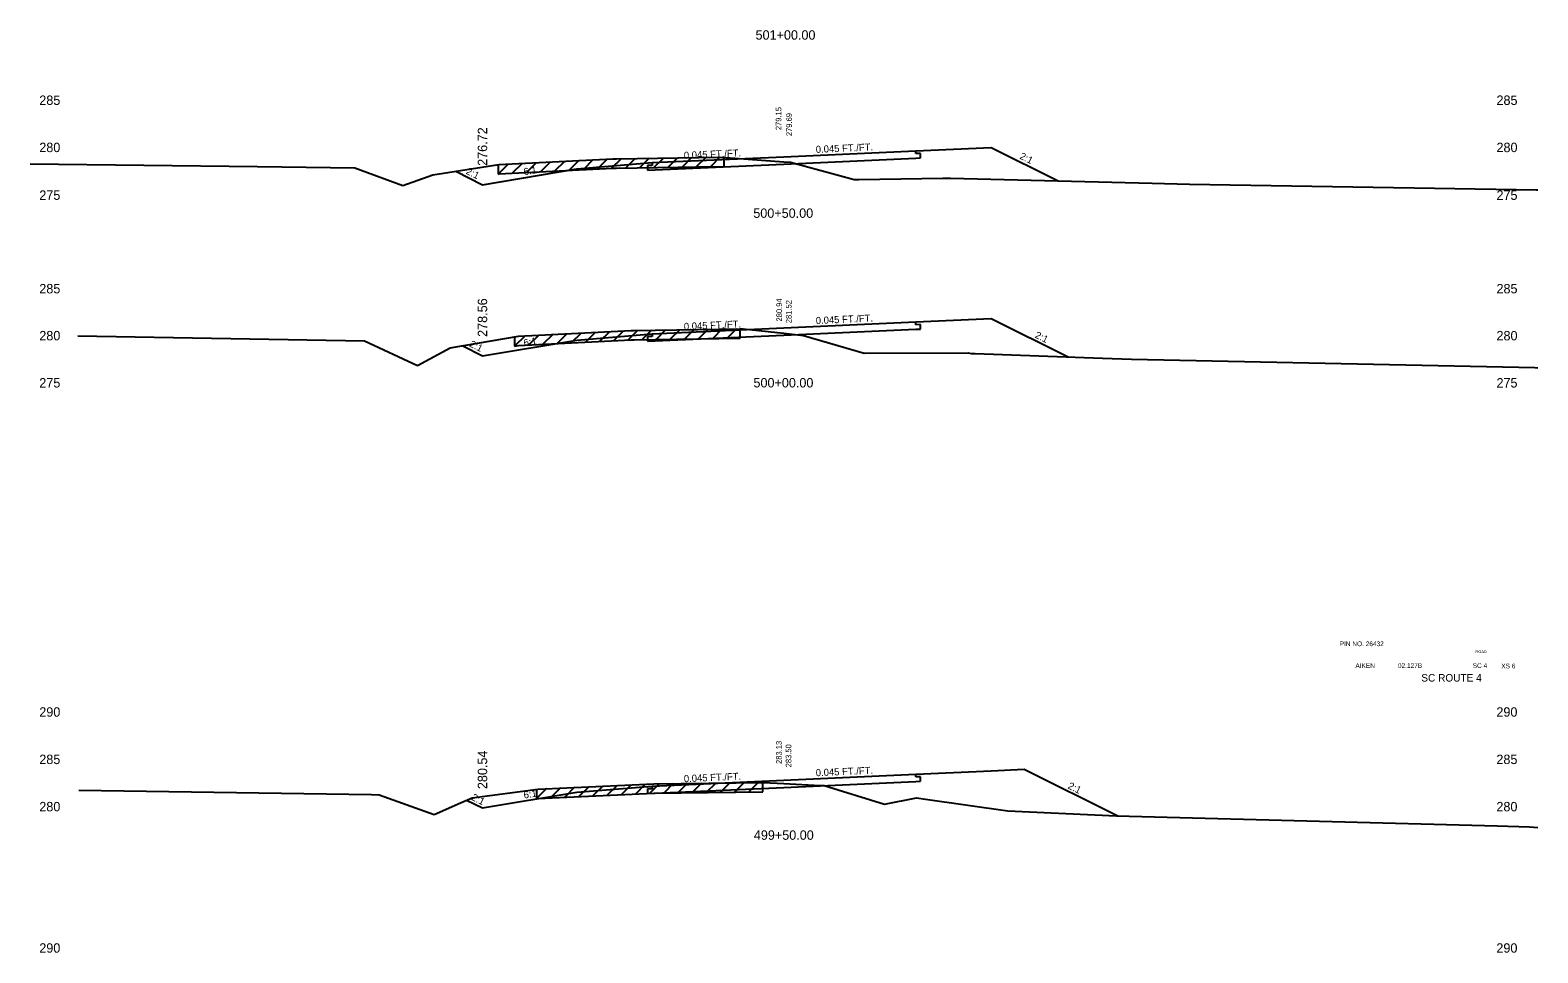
# Model space of a CAD drawing. Extents: x 883 to 1160, y 1002 to 4323.
# Drawn here: x 1000 to 1160, y 1645.2 to 1743.1 of the extents above; entities that cross this region are included whole.
import ezdxf

# ---------------------------------------------------------------- set-up
doc = ezdxf.new("R2010")
doc.units = 0
for name, color, linetype in [('Level 1', 7, 'Continuous'), ('Level 10', 7, 'Continuous'), ('Level 11', 7, 'Continuous'), ('Level 12', 7, 'Continuous'), ('Level 3', 7, 'Continuous'), ('Level 32', 7, 'Continuous'), ('Level 33', 7, 'Continuous'), ('Level 59', 7, 'Continuous'), ('Level 6', 7, 'Continuous'), ('Level 60', 7, 'Continuous'), ('Level 61', 7, 'Continuous'), ('Level 7', 7, 'Continuous')]:
    doc.layers.add(name, color=color, linetype=linetype)

msp = doc.modelspace()

# ---------------------------------------------------------------- linework, layer by layer
at = {"layer": 'Level 11'}
for p, q in [((1094, 1730.02), (1094, 1730.32)), ((1094.5, 1730.04), (1094, 1730.02)), ((1094.5, 1729.56), (1094.5, 1730.04)), ((1094, 1729.54), (1094.5, 1729.56)), ((1094, 1711.85), (1094, 1712.15)), ((1094.5, 1711.87), (1094, 1711.85)), ((1094, 1711.37), (1094.5, 1711.39)), ((1094.5, 1711.39), (1094.5, 1711.87)), ((1094, 1663.83), (1094, 1664.13)), ((1094.5, 1663.85), (1094, 1663.83)), ((1094, 1663.35), (1094.5, 1663.37)), ((1094.5, 1663.37), (1094.5, 1663.85))]:
    msp.add_line(p, q, dxfattribs=at)
at = {"layer": 'Level 12'}
for p, q in [((1065.5, 1728.28), (1080, 1728.91)), ((1066, 1728.76), (1065.5, 1728.76)), ((1065.5, 1728.76), (1065.5, 1728.28)), ((1066, 1729.06), (1066, 1728.76)), ((1080, 1728.91), (1094, 1729.54)), ((1065.5, 1710.11), (1080, 1710.74)), ((1066, 1710.59), (1065.5, 1710.59)), ((1065.5, 1710.59), (1065.5, 1710.11)), ((1066, 1710.89), (1066, 1710.59)), ((1080, 1710.74), (1094, 1711.37)), ((1065.5, 1662.09), (1080, 1662.72)), ((1066, 1662.57), (1065.5, 1662.57)), ((1065.5, 1662.57), (1065.5, 1662.09)), ((1066, 1662.87), (1066, 1662.57)), ((1080, 1662.72), (1094, 1663.35))]:
    msp.add_line(p, q, dxfattribs=at)
at = {"layer": 'Level 59'}
for p, q in [((1066, 1729.06), (1080, 1729.69)), ((1080, 1729.69), (1094, 1730.32)), ((1080, 1711.52), (1094, 1712.15)), ((1066, 1710.89), (1080, 1711.52)), ((1080, 1663.5), (1094, 1664.13)), ((1066, 1662.87), (1080, 1663.5))]:
    msp.add_line(p, q, dxfattribs=at)
at = {"layer": 'Level 6'}
for p, q in [((1094, 1730.32), (1102, 1730.68)), ((1058, 1728.39), (1066, 1729.06)), ((1094, 1712.15), (1102, 1712.51)), ((1058, 1710.22), (1066, 1710.89)), ((1094, 1664.13), (1102, 1664.49)), ((1102, 1664.49), (1105.5, 1664.65)), ((1058, 1662.2), (1066, 1662.87))]:
    msp.add_line(p, q, dxfattribs=at)
at = {"layer": 'Level 60'}
for p, q in [((1062.22, 1729.47), (1073.11, 1729.64)), ((1073.11, 1729.64), (1073.81, 1729.62)), ((1073.81, 1729.62), (1080, 1729.15)), ((1000, 1728.92), (1024.13, 1728.65)), ((1024.13, 1728.65), (1034.44, 1728.51)), ((1034.44, 1728.51), (1039.55, 1726.65)), ((1042.74, 1727.76), (1049.73, 1728.86)), ((1049.73, 1728.86), (1061.84, 1729.46)), ((1061.84, 1729.46), (1062.22, 1729.47)), ((1080, 1729.15), (1080.68, 1729.1)), ((1080.68, 1729.1), (1087.44, 1727.28)), ((1039.55, 1726.65), (1042.74, 1727.76)), ((1087.44, 1727.28), (1087.94, 1727.28)), ((1087.94, 1727.28), (1096.85, 1727.43)), ((1096.85, 1727.43), (1097.68, 1727.4)), ((1097.68, 1727.4), (1119.07, 1726.88)), ((1119.07, 1726.88), (1123.03, 1726.79)), ((1123.03, 1726.79), (1159.87, 1726.19)), ((1159.87, 1726.19), (1160, 1726.18)), ((1005.06, 1710.68), (1035.47, 1710.13)), ((1044.57, 1709.38), (1051.82, 1710.65)), ((1051.82, 1710.65), (1063.78, 1711.23)), ((1063.78, 1711.23), (1064.1, 1711.24)), ((1064.1, 1711.24), (1075.33, 1711.43)), ((1075.33, 1711.43), (1075.66, 1711.43)), ((1075.66, 1711.43), (1080, 1710.94)), ((1080, 1710.94), (1082.07, 1710.72)), ((1082.07, 1710.72), (1088.5, 1708.83)), ((1035.47, 1710.13), (1041.1, 1707.53)), ((1041.1, 1707.53), (1044.57, 1709.38)), ((1088.5, 1708.83), (1099.56, 1708.86)), ((1099.56, 1708.86), (1099.86, 1708.81)), ((1099.86, 1708.81), (1100.3, 1708.79)), ((1100.3, 1708.79), (1113.79, 1708.29)), ((1113.79, 1708.29), (1116.87, 1708.21)), ((1116.87, 1708.21), (1159.68, 1707.3)), ((1159.68, 1707.3), (1160, 1707.29)), ((1005.18, 1662.44), (1036.24, 1661.97)), ((1046.89, 1661.63), (1053.87, 1662.55)), ((1053.87, 1662.55), (1066.19, 1663.11)), ((1066.19, 1663.11), (1077.82, 1663.24)), ((1077.82, 1663.24), (1080, 1663.13)), ((1080, 1663.13), (1083.84, 1662.93)), ((1083.84, 1662.93), (1084.25, 1662.91)), ((1084.25, 1662.91), (1090.66, 1660.94)), ((1036.24, 1661.97), (1037.05, 1661.95)), ((1037.05, 1661.95), (1042.87, 1659.86)), ((1042.87, 1659.86), (1045.68, 1661.1)), ((1045.68, 1661.1), (1046.89, 1661.63)), ((1090.66, 1660.94), (1094.06, 1661.6)), ((1094.06, 1661.6), (1095.01, 1661.49)), ((1095.01, 1661.49), (1103.74, 1660.25)), ((1103.74, 1660.25), (1115.3, 1659.69)), ((1115.3, 1659.69), (1117.98, 1659.63)), ((1117.98, 1659.63), (1155.69, 1658.65)), ((1155.69, 1658.65), (1159.12, 1658.54)), ((1159.12, 1658.54), (1160, 1658.46))]:
    msp.add_line(p, q, dxfattribs=at)
at = {"layer": 'Level 61'}
for p, q in [((1071.7, 1729.62), (1070.69, 1728.61)), ((1073.2, 1729.64), (1072.19, 1728.63)), ((1073.64, 1728.63), (1073.64, 1729.63)), ((1050.72, 1728.91), (1049.65, 1727.85)), ((1049.65, 1728.85), (1049.65, 1727.85)), ((1049.73, 1727.86), (1061.84, 1728.46)), ((1052.21, 1728.98), (1051.16, 1727.93)), ((1053.71, 1729.05), (1052.66, 1728)), ((1055.21, 1729.13), (1054.16, 1728.08)), ((1056.72, 1729.2), (1055.66, 1728.15)), ((1058.22, 1729.28), (1057.17, 1728.23)), ((1059.72, 1729.35), (1058.67, 1728.3)), ((1061.22, 1729.43), (1060.17, 1728.37)), ((1062.71, 1729.48), (1061.67, 1728.45)), ((1061.84, 1728.46), (1062.22, 1728.47)), ((1062.22, 1728.47), (1073.11, 1728.64)), ((1064.19, 1729.5), (1063.17, 1728.49)), ((1065.69, 1729.53), (1064.68, 1728.51)), ((1067.2, 1729.55), (1066.18, 1728.54)), ((1068.7, 1729.57), (1067.68, 1728.56)), ((1070.2, 1729.6), (1069.18, 1728.58)), ((1073.11, 1728.64), (1073.64, 1728.63)), ((1049.65, 1727.85), (1049.73, 1727.86)), ((1052.52, 1710.68), (1051.41, 1709.58)), ((1051.41, 1710.58), (1051.41, 1709.58)), ((1053.97, 1710.75), (1052.91, 1709.7)), ((1055.47, 1710.82), (1054.41, 1709.77)), ((1056.97, 1710.9), (1055.92, 1709.85)), ((1058.47, 1710.97), (1057.42, 1709.92)), ((1059.97, 1711.04), (1058.92, 1709.99)), ((1061.47, 1711.11), (1060.42, 1710.06)), ((1062.97, 1711.19), (1061.92, 1710.14)), ((1064.46, 1711.25), (1063.42, 1710.21)), ((1064.1, 1710.24), (1075.33, 1710.43)), ((1065.94, 1711.27), (1064.92, 1710.25)), ((1067.44, 1711.3), (1066.43, 1710.28)), ((1068.94, 1711.32), (1067.93, 1710.3)), ((1070.45, 1711.35), (1069.43, 1710.33)), ((1071.95, 1711.37), (1070.93, 1710.35)), ((1073.45, 1711.4), (1072.43, 1710.38)), ((1074.95, 1711.42), (1073.93, 1710.4)), ((1075.33, 1710.43), (1075.36, 1710.43)), ((1075.36, 1710.43), (1075.36, 1711.43)), ((1051.41, 1709.58), (1051.82, 1709.65)), ((1051.82, 1709.65), (1063.78, 1710.23)), ((1063.78, 1710.23), (1064.1, 1710.24)), ((1054.79, 1662.59), (1053.73, 1661.53)), ((1053.73, 1662.53), (1053.73, 1661.53)), ((1056.28, 1662.66), (1055.23, 1661.61)), ((1057.78, 1662.73), (1056.73, 1661.68)), ((1059.28, 1662.79), (1058.23, 1661.75)), ((1060.78, 1662.86), (1059.73, 1661.81)), ((1062.28, 1662.93), (1061.23, 1661.88)), ((1063.78, 1663), (1062.73, 1661.95)), ((1065.28, 1663.06), (1064.23, 1662.02)), ((1066.76, 1663.11), (1065.73, 1662.08)), ((1068.24, 1663.13), (1067.23, 1662.12)), ((1069.74, 1663.15), (1068.73, 1662.13)), ((1071.25, 1663.16), (1070.23, 1662.15)), ((1072.75, 1663.18), (1071.73, 1662.17)), ((1074.25, 1663.2), (1073.23, 1662.18)), ((1075.75, 1663.21), (1074.73, 1662.2)), ((1077.25, 1663.23), (1076.23, 1662.22)), ((1077.75, 1662.24), (1077.75, 1663.24)), ((1053.73, 1661.53), (1053.87, 1661.55)), ((1053.87, 1661.55), (1066.19, 1662.11)), ((1066.19, 1662.11), (1077.75, 1662.24))]:
    msp.add_line(p, q, dxfattribs=at)
at = {"layer": 'Level 7'}
for p, q in [((1102, 1730.68), (1109.11, 1727.12)), ((1045.16, 1728.14), (1048, 1726.72)), ((1048, 1726.72), (1058, 1728.39)), ((1102, 1712.51), (1110.17, 1708.43)), ((1045.9, 1709.61), (1048, 1708.56)), ((1048, 1708.56), (1058, 1710.22)), ((1105.5, 1664.65), (1115.41, 1659.69)), ((1046.32, 1661.38), (1048, 1660.54)), ((1048, 1660.54), (1058, 1662.2))]:
    msp.add_line(p, q, dxfattribs=at)

# ---------------------------------------------------------------- texts
at = {"layer": 'Level 1'}
for s, height, p in [('501+00.00', 1, (1076.98, 1742.12)), ('500+50.00', 1, (1076.74, 1723.2)), ('500+00.00', 1, (1076.76, 1705.19)), ('PIN NO. 26432', 0.5, (1138.97, 1677.72)), ('AIKEN', 0.5, (1140.64, 1675.4)), ('02.127B', 0.5, (1145.15, 1675.4)), ('SC 4', 0.5, (1153.09, 1675.4)), ('XS 6', 0.5, (1156.12, 1675.36)), ('SC ROUTE 4', 0.8, (1147.63, 1673.96)), ('499+50.00', 1, (1076.8, 1657.16))]:
    msp.add_text(s, height=height, dxfattribs=at).set_placement(p)
at = {"layer": 'Level 10'}
for s, p in [('279.15', (1079.72, 1732.51)), ('280.94', (1079.79, 1712.19)), ('283.13', (1079.76, 1665.21))]:
    msp.add_text(s, height=0.6, rotation=90, dxfattribs=at).set_placement(p)
at = {"layer": 'Level 3'}
for s, height, p in [(' 285', 1, (1000.6, 1735.19)), (' 285', 1, (1155.24, 1735.19)), (' 280', 1, (1000.6, 1730.18)), (' 280', 1, (1155.24, 1730.18)), (' 275', 1, (1000.6, 1725.11)), (' 275', 1, (1155.24, 1725.11)), (' 285', 1, (1000.6, 1715.18)), (' 285', 1, (1155.24, 1715.18)), (' 280', 1, (1000.6, 1710.19)), (' 280', 1, (1155.24, 1710.19)), (' 275', 1, (1000.6, 1705.18)), (' 275', 1, (1155.24, 1705.18)), ('ROAD', 0.3, (1153.38, 1676.99)), (' 290', 1, (1000.6, 1670.23)), (' 290', 1, (1155.23, 1670.23)), (' 285', 1, (1000.6, 1665.2)), (' 285', 1, (1155.23, 1665.2)), (' 280', 1, (1000.6, 1660.18)), (' 280', 1, (1155.23, 1660.18)), (' 290', 1, (1000.6, 1645.17)), (' 290', 1, (1155.23, 1645.17))]:
    msp.add_text(s, height=height, dxfattribs=at).set_placement(p)
at = {"layer": 'Level 32'}
for s, rotation, p in [('0.045 FT./FT.', 2.5766, (1069.39, 1729.46)), ('0.045 FT./FT.', 2.5766, (1083.39, 1730.09)), ('2:1', 333.435, (1104.94, 1729.51)), ('2:1', 333.435, (1046.19, 1727.91)), ('6:1', 9.4623, (1052.43, 1727.72)), ('0.045 FT./FT.', 2.5766, (1069.39, 1711.29)), ('0.045 FT./FT.', 2.5766, (1083.39, 1711.92)), ('6:1', 9.4623, (1052.43, 1709.55)), ('2:1', 333.435, (1106.56, 1710.51)), ('2:1', 333.435, (1046.55, 1709.56)), ('0.045 FT./FT.', 2.5766, (1069.39, 1663.27)), ('0.045 FT./FT.', 2.5766, (1083.39, 1663.9)), ('6:1', 9.4623, (1052.43, 1661.53)), ('2:1', 333.435, (1110.06, 1662.65)), ('2:1', 333.435, (1046.76, 1661.43))]:
    msp.add_text(s, height=0.75, rotation=rotation, dxfattribs=at).set_placement(p)
at = {"layer": 'Level 33'}
for s, p in [('276.72', (1048.5, 1728.72)), ('278.56', (1048.5, 1710.56)), ('280.54', (1048.5, 1662.54))]:
    msp.add_text(s, height=1, rotation=90, dxfattribs=at).set_placement(p)
at = {"layer": 'Level 59'}
for s, p in [(' 279.69', (1080.84, 1731.65)), (' 281.52', (1080.8, 1711.79)), (' 283.50', (1080.78, 1664.63))]:
    msp.add_text(s, height=0.6, rotation=90, dxfattribs=at).set_placement(p)

doc.saveas('drawing.dxf')
